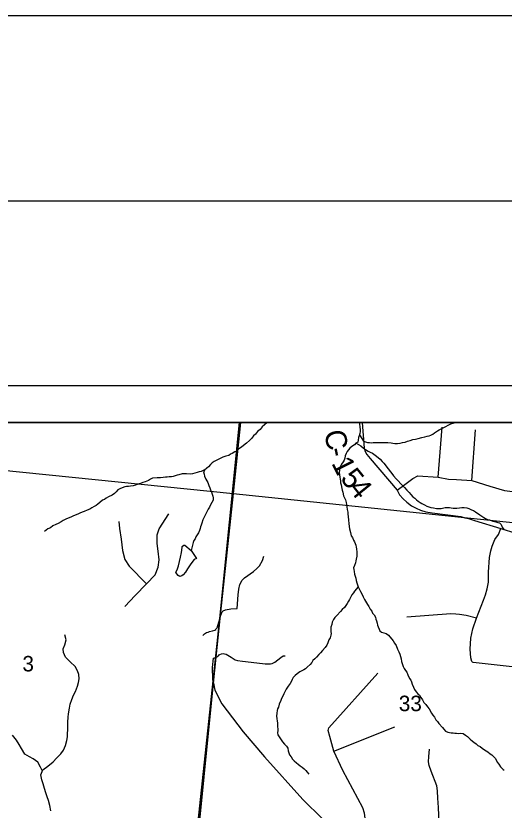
# Model space of a CAD drawing. Extents: x 0 to 34, y 0 to 22.
# Drawn here: x 3.46 to 4.78, y 19.852 to 22 of the extents above; entities that cross this region are included whole.
import ezdxf

# ---------------------------------------------------------------- set-up
doc = ezdxf.new("R2010")
doc.units = 0
for name, color, linetype in [('GM_X_Corporation', 7, 'Continuous'), ('GM_X_County_Road', 7, 'Continuous'), ('GM_X_County_Road_Text', 7, 'Continuous'), ('GM_X_Minor_Lake', 7, 'Continuous'), ('GM_X_Minor_River', 7, 'Continuous'), ('GM_X_Section_Text', 7, 'Continuous'), ('GM_X_State_Route', 7, 'Continuous'), ('GM_X_Township_Road', 7, 'Continuous'), ('SH_Border', 7, 'Continuous'), ('SH_Cut_Line', 7, 'Continuous'), ('SH_Data', 7, 'Continuous')]:
    doc.layers.add(name, color=color, linetype=linetype)

msp = doc.modelspace()

# ---------------------------------------------------------------- linework, layer by layer
at = {"layer": 'GM_X_Corporation'}
for points in [[(8.9, 14.3814), (8.9, 20.9), (2.1, 20.9)], [(3.4565, 17.7784), (3.4633, 17.7753), (3.4638, 17.7552), (3.4639, 17.7441), (3.744, 17.7149), (3.7454, 17.7286), (3.8023, 18.3182), (3.8126, 18.3974), (3.8234, 18.553), (3.8667, 18.9339), (3.918, 19.4442), (3.9936, 20.1954), (4.0006, 20.2658), (4.0111, 20.3696), (4.0645, 20.9), (2.1, 20.9)], [(8.9, 17.1766), (8.9, 20.9), (4.0645, 20.9), (4.0111, 20.3696), (4.0006, 20.2658), (3.9936, 20.1954), (3.918, 19.4442), (3.8667, 18.9339), (3.8234, 18.553), (3.8126, 18.3974), (3.8023, 18.3182), (3.7454, 17.7286)]]:
    msp.add_lwpolyline(points, dxfattribs=at)
for points in [[(4.0674, 20.9), (3.0509, 20.9), (3.042, 20.8099), (4.0476, 20.7082)], [(5.0731, 20.9), (4.0674, 20.9), (4.0476, 20.7082), (5.0456, 20.6041)], [(4.0476, 20.7082), (3.9403, 19.7031), (2.9428, 19.8144), (3.042, 20.8099)], [(4.0476, 20.7082), (5.0456, 20.6041), (4.9462, 19.5973), (3.9403, 19.7031)]]:
    msp.add_lwpolyline(points, close=True, dxfattribs=at)
at = {"layer": 'GM_X_County_Road'}
for points in [[(4.3962, 20.9), (4.4014, 20.8309), (4.4042, 20.8217), (4.4089, 20.8132), (4.4177, 20.8031), (4.4907, 20.7173), (4.4967, 20.7049), (4.5074, 20.6936), (4.517, 20.685), (4.5292, 20.6748), (4.542, 20.6684), (4.554, 20.6631), (4.5683, 20.6586), (4.5853, 20.6562), (4.6625, 20.6455), (4.6738, 20.6425), (4.6839, 20.6403), (4.7001, 20.6354), (4.7713, 20.6137)], [(4.8097, 20.2385), (4.6962, 20.251), (4.6948, 20.2516), (4.6937, 20.2526), (4.6928, 20.2541), (4.6897, 20.2637), (4.688, 20.2873), (4.69, 20.3169), (4.6956, 20.3418), (4.7053, 20.3708), (4.7246, 20.4197), (4.7296, 20.434), (4.7342, 20.4502), (4.7377, 20.4687), (4.7381, 20.4953), (4.7407, 20.5348), (4.7438, 20.5533), (4.7476, 20.5657), (4.7553, 20.5834), (4.7648, 20.5976), (4.7713, 20.6137)], [(4.7713, 20.6137), (4.8119, 20.6005), (4.8454, 20.5882), (4.8732, 20.5765), (4.8915, 20.5665), (4.9154, 20.5533), (4.939, 20.5402), (4.9587, 20.5256), (4.9851, 20.5048), (5.0263, 20.4698)]]:
    msp.add_lwpolyline(points, dxfattribs=at)
at = {"layer": 'GM_X_Minor_Lake'}
for points in [[(3.8955, 20.5013), (3.8996, 20.5122), (3.9022, 20.5239), (3.9052, 20.536), (3.9078, 20.5488), (3.9096, 20.5621), (3.9097, 20.5647), (3.9101, 20.5655), (3.914, 20.5688), (3.9163, 20.5687), (3.9338, 20.5542)], [(3.9338, 20.5542), (3.9484, 20.5326), (3.9422, 20.5293), (3.9324, 20.5182), (3.9237, 20.5047), (3.9181, 20.4954), (3.9119, 20.4883), (3.908, 20.485), (3.9026, 20.4836), (3.8985, 20.486), (3.8945, 20.491), (3.8923, 20.4957), (3.8955, 20.5013)]]:
    msp.add_lwpolyline(points, dxfattribs=at)
at = {"layer": 'GM_X_Minor_River'}
for points in [[(4.1386, 20.9), (4.138, 20.8994), (4.1317, 20.8943), (4.1254, 20.888), (4.1199, 20.881), (4.1132, 20.8755), (4.1077, 20.8685), (4.1022, 20.8637), (4.097, 20.8571), (4.0915, 20.8516), (4.0829, 20.8443), (4.0755, 20.8377), (4.0696, 20.8337), (4.0626, 20.8286), (4.0567, 20.8224), (4.0521, 20.8206), (4.0447, 20.8163), (4.0397, 20.8146), (4.0351, 20.8113), (4.0274, 20.8093), (4.0197, 20.8062), (4.012, 20.8026), (4.0031, 20.798), (3.9962, 20.7944), (3.9907, 20.7908), (3.9856, 20.7864), (3.9809, 20.7805), (3.9758, 20.7769), (3.9695, 20.7714), (3.9671, 20.7669), (3.9684, 20.7601), (3.9701, 20.7547), (3.9736, 20.7466), (3.9783, 20.7381), (3.9818, 20.7296), (3.9842, 20.7238), (3.9863, 20.718), (3.9888, 20.7122), (3.9908, 20.7061), (3.9925, 20.7007), (3.9931, 20.6961), (3.9933, 20.6904), (3.9897, 20.6837), (3.9861, 20.6777), (3.9828, 20.6714), (3.9792, 20.6654), (3.9759, 20.6587), (3.9714, 20.6497), (3.9686, 20.6438), (3.9653, 20.637), (3.9623, 20.628), (3.961, 20.6227), (3.9593, 20.6179), (3.958, 20.6133), (3.9563, 20.6077), (3.9535, 20.6021), (3.9502, 20.5965), (3.9466, 20.5909), (3.9445, 20.5853), (3.941, 20.5809), (3.9393, 20.576)], [(4.3884, 20.9), (4.3892, 20.8956), (4.39, 20.8884), (4.3905, 20.8804), (4.3904, 20.8758), (4.3898, 20.8701), (4.3881, 20.8641), (4.3864, 20.8592), (4.3854, 20.8528), (4.3848, 20.8471), (4.3794, 20.8443), (4.3751, 20.8395), (4.3685, 20.8355), (4.363, 20.8308), (4.3587, 20.8264), (4.3551, 20.8216), (4.353, 20.8159), (4.3502, 20.8103), (4.3488, 20.8039), (4.3471, 20.7983), (4.345, 20.7934), (4.3402, 20.7871), (4.3374, 20.7823), (4.3354, 20.7774), (4.3344, 20.771), (4.3342, 20.7653), (4.3347, 20.7588), (4.336, 20.7527), (4.3366, 20.7473), (4.3372, 20.7428), (4.3378, 20.737), (4.3391, 20.7313), (4.341, 20.7221), (4.3424, 20.7167), (4.3441, 20.7121), (4.346, 20.7018), (4.3485, 20.6968), (4.3506, 20.6906), (4.353, 20.6837), (4.354, 20.6787), (4.3545, 20.6722), (4.3558, 20.6646), (4.357, 20.6577), (4.3572, 20.652), (4.3578, 20.6459), (4.359, 20.636), (4.3598, 20.6272), (4.361, 20.6192), (4.3619, 20.6127), (4.3642, 20.6024), (4.3666, 20.5939), (4.3699, 20.5892), (4.373, 20.5819), (4.3752, 20.5773), (4.3786, 20.568), (4.38, 20.5634), (4.3809, 20.5581), (4.3818, 20.5493), (4.382, 20.544), (4.3814, 20.5383), (4.38, 20.5307), (4.3791, 20.5262), (4.3778, 20.5209), (4.3752, 20.5131), (4.3731, 20.5074), (4.3733, 20.5025), (4.3743, 20.4967), (4.3752, 20.4902), (4.3776, 20.4841), (4.3786, 20.4791), (4.3803, 20.4726), (4.382, 20.4665), (4.3837, 20.4611), (4.3854, 20.4561), (4.3914, 20.4429), (4.395, 20.4371), (4.3989, 20.4286), (4.4028, 20.4216), (4.4103, 20.4081), (4.4143, 20.4023)], [(4.3889, 20.867), (4.4001, 20.8496), (4.4054, 20.8479), (4.4102, 20.8463), (4.4155, 20.8457), (4.4212, 20.8455), (4.4262, 20.8461), (4.4311, 20.8463), (4.4357, 20.8465), (4.4501, 20.846), (4.4554, 20.8462), (4.4657, 20.8459), (4.4747, 20.8448), (4.4793, 20.8443), (4.4849, 20.8437), (4.4918, 20.8438), (4.4986, 20.8443), (4.5048, 20.8457), (4.512, 20.8473), (4.5185, 20.8494), (4.5255, 20.8518), (4.5331, 20.8538), (4.5404, 20.8554), (4.5473, 20.8571), (4.5576, 20.8594), (4.5653, 20.861), (4.5722, 20.8631), (4.5775, 20.8644), (4.5821, 20.8658), (4.5868, 20.8687), (4.5918, 20.8719), (4.5996, 20.8773), (4.6047, 20.8802), (4.6112, 20.8838), (4.6205, 20.8888), (4.6302, 20.8938), (4.636, 20.8962), (4.6448, 20.899), (4.6482, 20.9)], [(4.38, 20.8446), (4.3928, 20.8374), (4.3994, 20.8303), (4.405, 20.8274), (4.4121, 20.823), (4.4177, 20.8202), (4.4237, 20.8173), (4.4314, 20.8117), (4.4392, 20.8057), (4.4451, 20.8006), (4.4506, 20.7951), (4.4543, 20.7904), (4.4583, 20.7853), (4.4626, 20.7798), (4.4666, 20.7744), (4.4724, 20.767), (4.4761, 20.7623), (4.4811, 20.7556), (4.4881, 20.7478), (4.506, 20.7286), (4.5104, 20.7242), (4.5167, 20.7172), (4.5233, 20.7105), (4.528, 20.705), (4.5335, 20.6995), (4.5383, 20.6952), (4.5431, 20.6912), (4.5475, 20.6876), (4.5527, 20.684), (4.5579, 20.6808), (4.5643, 20.6775), (4.5713, 20.6739), (4.5766, 20.6718), (4.5815, 20.6705), (4.589, 20.6691), (4.5973, 20.6677), (4.6019, 20.6675), (4.6095, 20.668), (4.6209, 20.6699), (4.6263, 20.6701), (4.632, 20.6699), (4.6365, 20.6693), (4.6418, 20.6688), (4.652, 20.6684), (4.6589, 20.6693), (4.6658, 20.6706), (4.6722, 20.6704), (4.679, 20.6694), (4.685, 20.6673), (4.6917, 20.664), (4.6974, 20.6619), (4.7029, 20.6583), (4.714, 20.6503), (4.7193, 20.6471), (4.7248, 20.6435), (4.7293, 20.6403), (4.7349, 20.6382), (4.7401, 20.6365), (4.745, 20.6348), (4.7499, 20.6335), (4.7574, 20.6313), (4.7627, 20.63), (4.7672, 20.6287), (4.7724, 20.624), (4.7748, 20.6174), (4.7802, 20.6097)], [(3.9711, 20.7728), (3.9607, 20.7675), (3.9549, 20.7666), (3.9496, 20.7645), (3.9438, 20.7628), (3.9373, 20.7611), (3.9316, 20.7606), (3.9206, 20.7609), (3.9153, 20.7615), (3.9096, 20.7609), (3.9004, 20.759), (3.8954, 20.7576), (3.8908, 20.7559), (3.885, 20.7542), (3.8801, 20.7532), (3.874, 20.7531), (3.869, 20.7525), (3.8645, 20.7522), (3.858, 20.7517), (3.8504, 20.7508), (3.8416, 20.7504), (3.8294, 20.7493), (3.8233, 20.7468), (3.8182, 20.7436), (3.8136, 20.7411), (3.809, 20.7393), (3.8029, 20.7377), (3.7967, 20.7348), (3.789, 20.7332), (3.7833, 20.7311), (3.7771, 20.729), (3.7695, 20.7278), (3.7638, 20.7272), (3.7592, 20.727), (3.7546, 20.7264), (3.7469, 20.7232), (3.7411, 20.7208), (3.7357, 20.7176), (3.731, 20.7124), (3.7259, 20.7084), (3.7204, 20.704), (3.7104, 20.6987), (3.7042, 20.6951), (3.6992, 20.6922), (3.6938, 20.6897), (3.6871, 20.6835), (3.6813, 20.6792), (3.6766, 20.6759), (3.6715, 20.673), (3.6653, 20.6694), (3.6592, 20.6662), (3.6522, 20.6631), (3.6441, 20.6592), (3.6391, 20.6574), (3.6326, 20.6546), (3.6272, 20.6521), (3.6202, 20.6493), (3.6141, 20.6469), (3.6079, 20.6441), (3.601, 20.6413), (3.5944, 20.6385), (3.5875, 20.6353), (3.5817, 20.6317), (3.5739, 20.627), (3.5678, 20.6246), (3.5596, 20.6203), (3.553, 20.6156), (3.5465, 20.6127), (3.5414, 20.6091), (3.537, 20.6057)], [(3.9393, 20.576), (3.9393, 20.576), (3.9338, 20.5542)], [(4.3857, 20.4555), (4.3751, 20.4443), (4.3723, 20.4398), (4.3683, 20.4342), (4.3618, 20.4215), (4.359, 20.4167), (4.3554, 20.4107), (4.3521, 20.4048), (4.3482, 20.4), (4.3423, 20.3941), (4.3371, 20.389), (4.3277, 20.3779), (4.3218, 20.3724), (4.3185, 20.3672), (4.3153, 20.3601), (4.3139, 20.354), (4.3114, 20.3469), (4.3112, 20.3401), (4.3117, 20.3343), (4.3119, 20.3294), (4.3118, 20.3245), (4.3093, 20.3181), (4.3064, 20.3121), (4.3031, 20.3042), (4.3006, 20.2979), (4.2958, 20.2912), (4.2891, 20.2838), (4.2832, 20.2776), (4.2788, 20.2724), (4.2725, 20.2654), (4.2682, 20.261), (4.2631, 20.2562), (4.2602, 20.2506), (4.2551, 20.2455), (4.2473, 20.2385), (4.2433, 20.2341), (4.2383, 20.2312), (4.2325, 20.2284), (4.2271, 20.2255), (4.2201, 20.2208), (4.215, 20.2157), (4.2099, 20.2102), (4.2067, 20.205), (4.2046, 20.2005), (4.201, 20.1941), (4.1958, 20.1867), (4.1909, 20.1785), (4.1844, 20.1666), (4.1816, 20.1602), (4.1783, 20.1539), (4.1758, 20.1482), (4.1721, 20.1381), (4.1695, 20.1306), (4.1675, 20.1261), (4.1666, 20.1212), (4.1652, 20.1137), (4.1645, 20.1057), (4.1654, 20.0992), (4.1663, 20.0923), (4.1673, 20.0874), (4.1675, 20.0813), (4.1677, 20.0668), (4.1675, 20.0611), (4.1681, 20.0558), (4.1803, 20.036), (4.1862, 20.0301), (4.1913, 20.025), (4.1953, 20.0195), (4.1962, 20.0119), (4.1979, 20.0069), (4.1996, 20.0015), (4.204, 19.9956), (4.2076, 19.9894), (4.212, 19.9851), (4.2182, 19.9796), (4.2234, 19.9756), (4.2282, 19.9712), (4.2341, 19.9676), (4.2389, 19.9636), (4.2441, 19.9593), (4.2477, 19.9546), (4.2521, 19.9491)], [(4.4143, 20.4023), (4.4179, 20.3957), (4.4222, 20.3902), (4.4243, 20.3848), (4.4283, 20.3797), (4.4319, 20.3735), (4.4329, 20.3685), (4.435, 20.3639), (4.4367, 20.357), (4.4376, 20.352), (4.439, 20.3474), (4.4418, 20.3413), (4.4443, 20.3366), (4.4487, 20.3334), (4.4551, 20.3313), (4.4608, 20.3296), (4.4671, 20.3252), (4.4711, 20.3201), (4.4765, 20.3138), (4.4798, 20.3092), (4.4838, 20.3033), (4.4877, 20.2971), (4.4916, 20.2875), (4.4951, 20.2797), (4.4983, 20.2732), (4.4996, 20.2674), (4.5013, 20.2609), (4.5029, 20.2533), (4.5067, 20.2406), (4.5099, 20.2344), (4.5135, 20.2297), (4.5168, 20.225), (4.5195, 20.2177), (4.5245, 20.2077), (4.5278, 20.203), (4.5299, 20.1984), (4.5316, 20.1922), (4.5347, 20.1841), (4.5379, 20.1776), (4.5419, 20.1721), (4.5466, 20.1666), (4.551, 20.1623), (4.555, 20.1561), (4.5593, 20.1498), (4.5633, 20.1432), (4.5684, 20.1374), (4.5731, 20.1307), (4.5771, 20.1253), (4.5835, 20.114), (4.5875, 20.109), (4.5919, 20.1031), (4.5954, 20.0958), (4.6002, 20.0918), (4.6035, 20.086), (4.613, 20.075), (4.617, 20.0703), (4.6217, 20.0656), (4.6277, 20.0627), (4.6322, 20.0614), (4.6371, 20.0609), (4.6424, 20.0607), (4.647, 20.0598), (4.6515, 20.0596), (4.6565, 20.0594), (4.6633, 20.0596), (4.6693, 20.0586), (4.676, 20.0546), (4.6812, 20.0506), (4.6878, 20.0439), (4.6941, 20.038), (4.6985, 20.0352), (4.7041, 20.0312), (4.7092, 20.0268), (4.7148, 20.024), (4.7208, 20.0196), (4.7271, 20.0152), (4.7315, 20.0124), (4.7364, 20.0096), (4.7419, 20.0044), (4.7467, 20.0016), (4.7511, 19.9965), (4.7555, 19.9918), (4.7594, 19.9856), (4.7608, 19.981), (4.7656, 19.9762), (4.7699, 19.9692), (4.7772, 19.9618), (4.7798, 19.9601)], [(3.5544, 19.85), (3.5514, 19.8645), (3.548, 19.8776), (3.5441, 19.8879), (3.5406, 19.8987), (3.5371, 19.9098), (3.5333, 19.9228), (3.5302, 19.9332), (3.5275, 19.947), (3.5329, 19.9609), (3.5457, 19.9704), (3.5605, 19.9825), (3.5699, 19.9921), (3.5812, 20.004), (3.5884, 20.014), (3.5937, 20.0268), (3.5978, 20.0396), (3.5993, 20.0498), (3.5995, 20.0593), (3.6002, 20.0692), (3.6005, 20.0795), (3.6004, 20.0893), (3.6012, 20.103), (3.6022, 20.1125), (3.6042, 20.1276), (3.6068, 20.1386), (3.6109, 20.151), (3.6158, 20.1626), (3.6207, 20.1728), (3.6264, 20.1867), (3.629, 20.1972), (3.6304, 20.2071), (3.6296, 20.2189), (3.6265, 20.2289), (3.6196, 20.2401), (3.6066, 20.2526), (3.5937, 20.2655), (3.5884, 20.2782), (3.5879, 20.2881), (3.592, 20.2987), (3.5958, 20.3126), (3.5917, 20.3257)], [(3.5315, 19.9572), (3.5263, 19.9679), (3.519, 19.9814), (3.5064, 19.9905), (3.4963, 19.9954), (3.484, 20.0033), (3.4749, 20.0184), (3.4684, 20.0289), (3.4615, 20.0408), (3.4505, 20.0548)]]:
    msp.add_lwpolyline(points, dxfattribs=at)
at = {"layer": 'GM_X_State_Route'}
msp.add_lwpolyline([(3.9932, 20.2631), (3.9906, 20.2378), (3.9917, 20.2047), (3.9938, 20.1949), (3.9979, 20.1765), (4.0167, 20.1396), (4.0741, 20.0638), (4.132, 19.9957), (4.2358, 19.8805), (4.2884, 19.828)], dxfattribs=at)
at = {"layer": 'GM_X_Township_Road'}
for p, q in [((4.6018, 20.7523), (4.6126, 20.8874)), ((4.693, 20.7431), (4.7025, 20.8806)), ((4.3197, 20.0109), (4.4841, 20.0771))]:
    msp.add_line(p, q, dxfattribs=at)
for points in [[(4.4907, 20.7173), (4.5119, 20.7321), (4.5335, 20.7489), (4.5463, 20.7555), (4.6018, 20.7523), (4.6296, 20.7471), (4.6514, 20.7457), (4.693, 20.7431), (4.7418, 20.728)], [(4.7418, 20.728), (4.7809, 20.7159), (4.8172, 20.7115)], [(3.7545, 20.4029), (3.7821, 20.432), (3.8129, 20.4638), (3.8359, 20.4884), (3.844, 20.5088), (3.8472, 20.5286), (3.8445, 20.5517), (3.8418, 20.5731), (3.8413, 20.5961), (3.8467, 20.6122), (3.8735, 20.653)], [(3.7379, 20.6321), (3.7395, 20.6133), (3.7448, 20.5844), (3.7481, 20.5543), (3.7539, 20.5292), (3.7663, 20.5115), (3.8129, 20.4638)], [(4.014, 20.3788), (4.0153, 20.3837), (4.0171, 20.388), (4.0198, 20.3907), (4.0263, 20.3931), (4.0408, 20.3958), (4.0579, 20.397), (4.0609, 20.4338), (4.0622, 20.449), (4.0652, 20.4622), (4.0713, 20.4734), (4.0779, 20.4796), (4.1025, 20.4969), (4.1113, 20.505), (4.1181, 20.5123), (4.1265, 20.5273), (4.1304, 20.539)], [(4.0007, 20.3412), (4.0037, 20.3452), (4.0114, 20.3691), (4.014, 20.3788)], [(4.7053, 20.3708), (4.6774, 20.3779), (4.6595, 20.3806), (4.6492, 20.3816), (4.6362, 20.3825), (4.5171, 20.3734)], [(3.9653, 20.324), (3.9699, 20.3285), (3.9749, 20.3319), (3.9794, 20.3334), (3.9829, 20.3347), (3.9913, 20.3368), (3.9974, 20.3385), (4.0001, 20.3404), (4.0007, 20.3412)], [(3.9932, 20.2631), (3.9964, 20.2634), (4.0009, 20.2653), (4.0023, 20.2659)], [(4.0023, 20.2659), (4.0036, 20.2665), (4.0055, 20.2678), (4.0075, 20.2694), (4.0093, 20.2713), (4.0116, 20.2727), (4.0156, 20.2746), (4.02, 20.2753), (4.0239, 20.2749), (4.0284, 20.2735), (4.0329, 20.2712), (4.0422, 20.2653), (4.0476, 20.2614), (4.0523, 20.2584), (4.0588, 20.2562), (4.0721, 20.2547), (4.1265, 20.2484), (4.1337, 20.2477), (4.1387, 20.247), (4.1431, 20.247), (4.1479, 20.2472), (4.1531, 20.2485), (4.1595, 20.2515), (4.1761, 20.2649), (4.1823, 20.2687), (4.1878, 20.2692)], [(4.403, 19.7848), (4.4038, 19.8302), (4.4027, 19.8431), (4.3977, 19.8581), (4.3435, 19.9586), (4.3197, 20.0109), (4.3088, 20.0507), (4.3043, 20.067), (4.306, 20.0742), (4.4384, 20.2221)], [(4.5635, 19.7225), (4.5793, 19.7388), (4.5929, 19.7582), (4.6009, 19.7776), (4.6045, 19.7969), (4.6046, 19.8126), (4.6031, 19.8394), (4.6025, 19.8583), (4.6019, 19.8725), (4.6011, 19.8832), (4.5997, 19.9041), (4.598, 19.9176), (4.5826, 19.9571), (4.5773, 19.9721), (4.5757, 19.9823), (4.5763, 19.9967), (4.5783, 20.0166)]]:
    msp.add_lwpolyline(points, dxfattribs=at)
at = {"layer": 'SH_Border'}
msp.add_lwpolyline([(1.5, 21.5), (33.5, 21.5), (33.5, 0.5), (1.5, 0.5)], close=True, dxfattribs=at)
at = {"layer": 'SH_Cut_Line'}
msp.add_lwpolyline([(0, 0), (34, 0), (34, 22), (0, 22)], close=True, dxfattribs=at)
at = {"layer": 'SH_Data'}
for p, q in [((2, 21), (9, 21)), ((2.1, 20.9), (8.9, 20.9))]:
    msp.add_line(p, q, dxfattribs=at)

# ---------------------------------------------------------------- texts
at = {"layer": 'GM_X_County_Road_Text'}
for s, rotation, p in [('C', 280.28, (4.2934, 20.8753)), ('-', 282.0745, (4.3021, 20.8279)), ('1', 296.6444, (4.3121, 20.7904)), ('5', 309.0137, (4.3349, 20.7481)), ('4', 309.0164, (4.3568, 20.7211))]:
    msp.add_text(s, height=0.0568, rotation=rotation, dxfattribs=at).set_placement(p)
at = {"layer": 'GM_X_Section_Text'}
for s, height, p in [('3', 0.0419, (3.4773, 20.2269)), ('33', 0.04186, (4.4952, 20.1194))]:
    msp.add_text(s, height=height, rotation=0, dxfattribs=at).set_placement(p)

doc.saveas('drawing.dxf')
